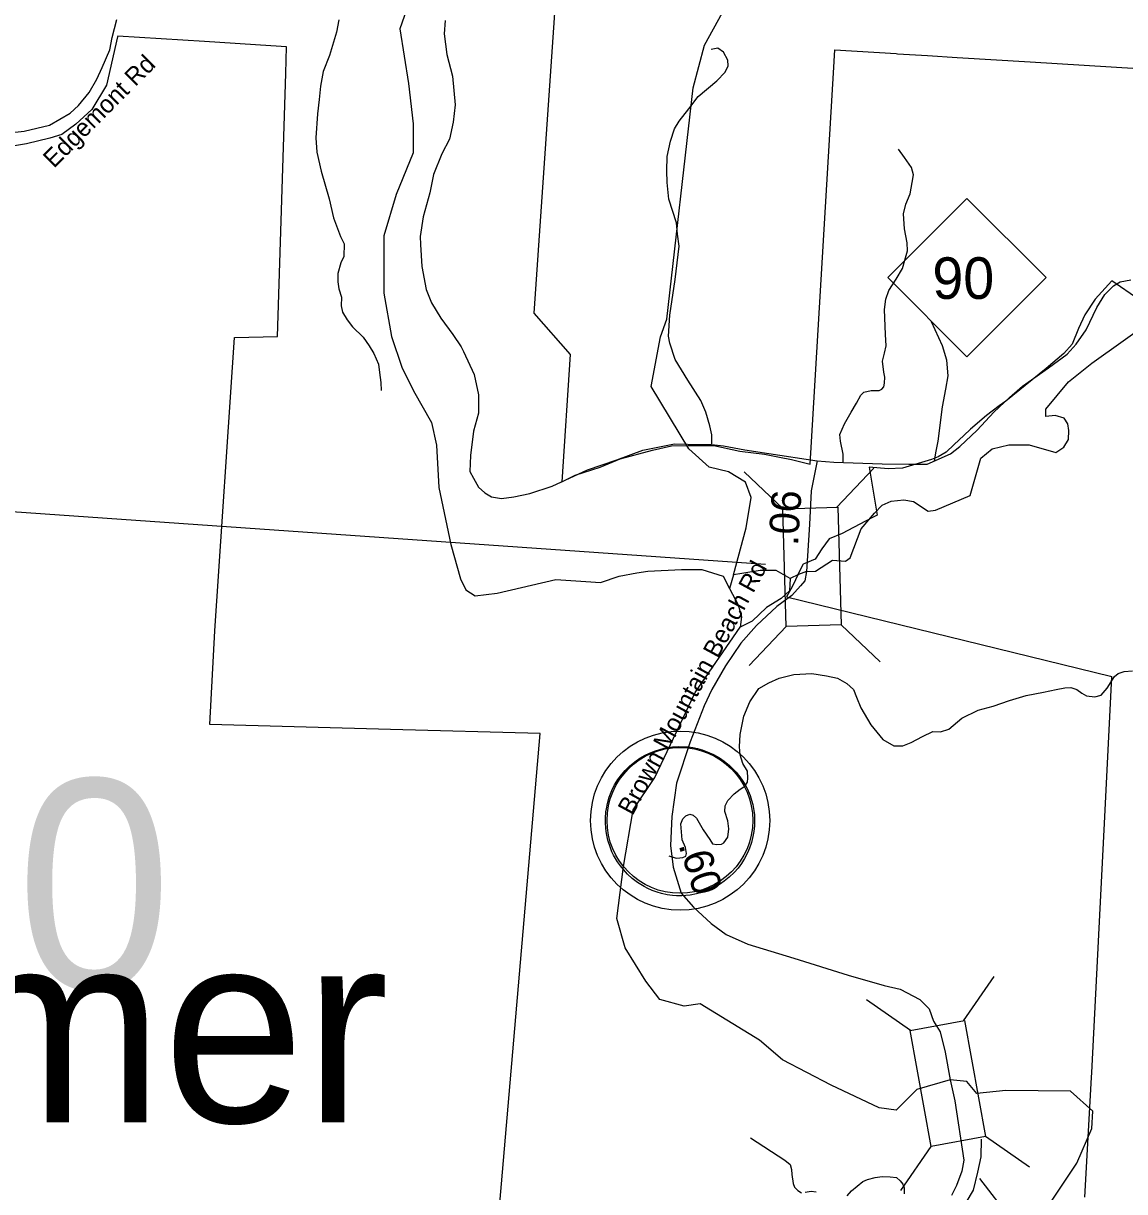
# Model space of a CAD drawing. Extents: x 1159738 to 1321356, y 736314 to 882035.
# Drawn here: x 1180449 to 1185086, y 823694 to 828611 of the extents above; entities that cross this region are included whole.
import ezdxf

# ---------------------------------------------------------------- set-up
doc = ezdxf.new("R2010")
doc.units = 0
for name, color, linetype in [('Exist Boundary Land Use Forest National US Forest Service', 7, 'Continuous'), ('Exist Civil Demographics Community CELL', 7, 'Continuous'), ('Exist Civil Demographics Community Label', 7, 'Continuous'), ('Exist Geographical Mountain Summit Elevation Number Label', 7, 'Continuous'), ('Exist Hydrographic Creek Single Shore', 7, 'Continuous'), ('Exist Road Non-System Type 51', 7, 'Continuous'), ('Exist Road Primary NC Label', 7, 'Continuous'), ('Exist Road Primary NC Shield CELL', 7, 'Continuous'), ('Exist Road Primary NC Shield Number Label', 7, 'Continuous'), ('Exist Road Primary NC Unpaved Attributed', 7, 'Continuous'), ('Exist Road Secondary Mileage Hundredths English Label', 7, 'Continuous'), ('Exist Road Secondary Structure Standard Bridge CELL', 7, 'Continuous'), ('Exist Road Secondary Structure Standard Bridge Number Label', 7, 'Continuous'), ('Exist Road Secondary Type 41 Attributed', 7, 'Continuous'), ('Exist Road Secondary Type 51 Label', 7, 'Continuous')]:
    doc.layers.add(name, color=color, linetype=linetype)

msp = doc.modelspace()

# ---------------------------------------------------------------- linework, layer by layer
at = {"layer": 'Exist Boundary Land Use Forest National US Forest Service'}
for points in [[(1182733.1, 829348.1), (1182598.4, 827391.9), (1182751.4, 827216.9), (1182716.4, 826681.9), (1182772.4, 826709.9), (1182877.4, 826742.9), (1182962.4, 826778.9), (1183097.4, 826814.9), (1183178.4, 826832.9), (1183248.3, 826834.9), (1183254, 826834.8), (1183356.4, 826833.9), (1183465.4, 826810.9), (1183569.3, 826797.9), (1183632.9, 826785.1), (1183683.3, 826774.9), (1183762.4, 826755.9), (1183859.6, 828403.4), (1183865.2, 828499.9), (1184123.6, 828483.9), (1184129.7, 828483.6), (1184255.3, 828475.7), (1184381, 828468), (1184688.9, 828448.9), (1185575.4, 828394)], [(1181077.2, 821985.4), (1181096, 822331.8), (1181167.4, 823654.7), (1182450.4, 823595.7), (1182625.4, 825621.8), (1181994.3, 825639.1), (1181234.4, 825659.8), (1181255.3, 826054.8), (1181338.3, 827288.9), (1181518.2, 827293.9), (1181553.8, 828399.8), (1181557.3, 828511.9), (1181490.6, 828516.2), (1181211.2, 828534.3), (1180846.2, 828557.9), (1180845.6, 828555), (1180799.3, 828350.9), (1180737.3, 828248.9), (1180670.2, 828186.9), (1180611.3, 828143.9), (1180560.2, 828127.9), (1180461.3, 828103.9), (1180360.3, 828086.9)], [(1185259.6, 827371), (1185032.4, 827526.9), (1184962.4, 827450.9), (1184918.4, 827383.9), (1184891.4, 827326.9), (1184865.4, 827260.9)], [(1184865.4, 827260.9), (1184830.4, 827221.9), (1184756.4, 827158), (1184586.4, 827020.9), (1184558.4, 827000.9), (1184504.4, 826960.9), (1184436.4, 826902.9), (1184408.6, 826876.6), (1184368.3, 826838.2), (1184334.4, 826805.9), (1184301.4, 826786.9), (1184273.4, 826775.9), (1184150.4, 826738.9), (1184090.4, 826736.9), (1184010.4, 826742.9), (1184044.3, 826541.9), (1184021, 826529.6), (1183994.4, 826515.6), (1183896.4, 826463.9), (1183841.3, 826441.9), (1183810.4, 826398.9), (1183783.4, 826355.9), (1183738.9, 826337.5), (1183732.4, 826334.9), (1183721.8, 826313.5), (1183688.4, 826245.9), (1183679.9, 826229.8), (1183662.3, 826196.9), (1185026.7, 825863), (1185031.4, 825861.9), (1185002.8, 825299.1), (1184946.4, 824195.8), (1184945.2, 824175.1), (1184917, 823671.3)]]:
    msp.add_lwpolyline(points, dxfattribs=at)
at = {"layer": 'Exist Civil Demographics Community CELL'}
msp.add_lwpolyline([(1182904, 825305.2), (1182908, 825327.5), (1182915.1, 825353.8), (1182926.8, 825382.6), (1182938.5, 825405.6), (1182951.8, 825428.5), (1182966.9, 825449), (1182982.7, 825466.5), (1183001.1, 825484.9), (1183023.2, 825503.3), (1183044.9, 825517.9), (1183064.4, 825529.3), (1183084.7, 825539.2), (1183106.5, 825548.3), (1183129, 825555.6), (1183146.4, 825560.2), (1183165.8, 825563.2), (1183182.3, 825566.1), (1183207.7, 825567.1), (1183225.5, 825566.7), (1183248.1, 825565.7), (1183267.7, 825562.7), (1183287.3, 825558.8), (1183307.4, 825553.1), (1183328, 825545.4), (1183354.6, 825533.7), (1183379.7, 825519.7), (1183399.9, 825505.5), (1183420.6, 825489.5), (1183433.9, 825477), (1183450.3, 825459.4), (1183465.8, 825440.6), (1183478.1, 825422.3), (1183490.6, 825402.2), (1183500.4, 825381.6), (1183508.6, 825361.5), (1183514.8, 825341.5), (1183520, 825323.1), (1183524.3, 825298.9), (1183526.8, 825280.1), (1183527.9, 825256.1), (1183527.2, 825233), (1183524.9, 825210.2), (1183521.1, 825188.3), (1183514.5, 825163.7), (1183507, 825140.3), (1183497.8, 825120.1), (1183485.2, 825096.1), (1183472.1, 825074.8), (1183458.3, 825056), (1183441.4, 825037), (1183420.2, 825017.2), (1183400.1, 825000.7), (1183380.1, 824986.9), (1183362.8, 824976.9), (1183335.6, 824963.9), (1183307, 824953.1), (1183283.2, 824947.2), (1183256.8, 824942), (1183239, 824940.1), (1183221.1, 824939.1), (1183198.7, 824939.1), (1183181.6, 824940.8), (1183159.1, 824943.7), (1183135.4, 824948.9), (1183117, 824954.1), (1183096.4, 824961.6), (1183078, 824969.6), (1183062.3, 824978.5), (1183035.1, 824994.8), (1183012.8, 825011.9), (1182993.2, 825029.9), (1182975.3, 825049.3), (1182962.6, 825065.2), (1182950.7, 825081.9), (1182934.3, 825110.2), (1182927.4, 825124.4), (1182920.5, 825140.5), (1182910.2, 825173.3), (1182904, 825201.5), (1182901.3, 825222.1), (1182900, 825247.4), (1182899.8, 825266.2), (1182901.9, 825292)], close=True, dxfattribs=at)
for centre, radius in [((1183214.5, 825255.5), 377.3), ((1183213.4, 825256.6), 306.8)]:
    msp.add_circle(centre, radius, dxfattribs=at)
at = {"layer": 'Exist Hydrographic Creek Single Shore'}
for points in [[(1183438.9, 826290.1), (1183492.7, 826487.5), (1183513.2, 826615.7), (1183490.1, 826679.8), (1183418.4, 826723.3), (1183336.4, 826743.8), (1183251.3, 826819.8), (1183092.3, 827082.3), (1183131.3, 827291.7), (1183158.3, 827366.6), (1183269.3, 828339.3), (1183316.3, 828518.9), (1183430.3, 828726.7), (1183749.3, 829091.2), (1184045.3, 829551.4), (1184334, 830291.9)], [(1182080, 828722), (1182033.9, 828588.7), (1182069.8, 828358), (1182090.3, 828188.8), (1182090.3, 828065.7), (1182018.6, 827891.4), (1181967.3, 827717.1), (1181967.3, 827476.1), (1181999.2, 827293.2), (1182041.8, 827164.3), (1182091.8, 827065.2), (1182167.2, 826931.2), (1182188.8, 826836.4), (1182197.6, 826658.4), (1182248.9, 826417.4), (1182289.9, 826273.8), (1182312.5, 826227.5), (1182351.3, 826202.1), (1182443.6, 826212.3), (1182690.4, 826271), (1182817.9, 826262.4), (1182879.1, 826257.2), (1182957.1, 826284.3), (1183031.3, 826299), (1183077.8, 826305.9), (1183220, 826311.9), (1183305.3, 826311.9), (1183395.8, 826284.3), (1183422.2, 826232.8)], [(1183746.8, 826303.7), (1183784.5, 826305.9), (1183856.1, 826351.6), (1183910.4, 826347.3), (1183930.6, 826362.1), (1183976.7, 826484.3), (1184033.1, 826549.3), (1184064.6, 826583.4), (1184102.6, 826599.8), (1184156, 826605.7), (1184197.4, 826598.1), (1184258.6, 826557.6), (1184289.6, 826561.9), (1184435.3, 826623.6), (1184480.9, 826780.8), (1184528.3, 826820.4), (1184599, 826837.7), (1184684.3, 826837.7), (1184796.8, 826805.3), (1184830.4, 826826.9), (1184849.4, 826859.6), (1184851.1, 826897.6), (1184846.8, 826926), (1184832.1, 826949.3), (1184793.7, 826961.2), (1184754.6, 826957), (1184754.6, 826988.1), (1184850.1, 827102.2), (1184947.4, 827181.7), (1185465.4, 827550.3)], [(1183677.1, 826274.7), (1183618.2, 826308), (1183551.6, 826308), (1183474.7, 826295.2), (1183438.9, 826290.1)], [(1183746.8, 826303.7), (1183712.1, 826292.1), (1183677.1, 826274.7), (1183674.6, 826223.4), (1183639.6, 826191), (1183578, 826152.6), (1183518.3, 826095.2), (1183467, 826069.6)], [(1183438.9, 826290.1), (1183422.2, 826232.8)], [(1183422.2, 826232.8), (1183459.4, 826164.5), (1183472.2, 826113.2), (1183467, 826069.6)], [(1184351.6, 824164.1), (1184211.7, 824124.2), (1184124.4, 824036.9), (1184053, 824046.8), (1183850.5, 824142.4), (1183645.4, 824248.2), (1183548.7, 824332.2), (1183298.2, 824484.8), (1183231.6, 824474.6), (1183129.1, 824502.8), (1183070.2, 824579.7), (1182983.1, 824720.7), (1182947.2, 824843.7), (1182975.3, 825063.2), (1183016.3, 825301.6), (1183108.5, 825437.5), (1183277.5, 825795.3), (1183467, 826069.6)], [(1184640.4, 823447.1), (1184884.4, 823813.2), (1184947.5, 823960.4), (1184952.6, 824032.2), (1184857.8, 824116.8), (1184586.3, 824119.4), (1184463.3, 824106.6), (1184422.3, 824157.8), (1184351.6, 824164.1)]]:
    msp.add_lwpolyline(points, dxfattribs=at)
at = {"layer": 'Exist Road Non-System Type 51'}
for points in [[(1181776.6, 828625.5), (1181767, 828574), (1181738.1, 828475.5), (1181711.3, 828409.1), (1181699.6, 828347), (1181694.2, 828290.2), (1181687.8, 828230.3), (1181680.4, 828129.3), (1181684.6, 828069.3), (1181702.8, 827989), (1181736, 827873.3), (1181754.2, 827793), (1181784, 827714.6), (1181800.1, 827683.5), (1181798, 827630), (1181786.2, 827603.2), (1181773.3, 827558.2), (1181772.3, 827522.9), (1181776.6, 827494), (1181788.3, 827458.6), (1181787.3, 827422.2), (1181792.6, 827395.4), (1181811.8, 827363.8), (1181834.2, 827333.8), (1181880.2, 827289.9), (1181904.9, 827254.6), (1181925.2, 827221.4), (1181944.5, 827176.4), (1181948.7, 827142.1), (1181954.1, 827100.3), (1181955.2, 827066.1)], [(1183348.4, 826841.3), (1183348.4, 826879.8), (1183339.8, 826917.3), (1183322.7, 826975.1), (1183301.3, 827024.4), (1183246.7, 827109), (1183193.2, 827196.8), (1183171, 827264.8), (1183165.7, 827294.8), (1183171, 827382.6), (1183193.5, 827533.6), (1183210.6, 827672.8), (1183203.1, 827724.2), (1183198.8, 827771.3), (1183166.8, 827871.2), (1183159.3, 827940.8), (1183158.2, 827991.1), (1183159.3, 828051.1), (1183174.3, 828115.3), (1183190.3, 828166.7), (1183210.7, 828199.9), (1183251.3, 828251.3), (1183289.7, 828304.1), (1183368.9, 828369.4), (1183404.2, 828405.8), (1183416, 828432.6), (1183414.9, 828456.1), (1183396.7, 828490.4), (1183373.2, 828506.5), (1183345.3, 828501.1)], [(1183901, 826762.3), (1183901, 826798.7), (1183889.2, 826853.4), (1183887, 826881.2), (1183906.3, 826926.2), (1183934.1, 826975.4), (1183956.6, 827012.9), (1183975.9, 827046.1), (1183987.6, 827059), (1184018.7, 827065.4), (1184052.9, 827065.4), (1184063.6, 827071.8), (1184072.2, 827081.5), (1184075.4, 827097.5), (1184076.5, 827122.2), (1184072.2, 827142.5), (1184066.8, 827189.6), (1184075.4, 827222.8), (1184081.8, 827253.9), (1184078.6, 827301), (1184074.3, 827407.4), (1184080.7, 827450.2), (1184093.6, 827486.6), (1184124.6, 827534.8), (1184150.3, 827579.8), (1184161, 827615.1), (1184171.7, 827653.7), (1184170.6, 827686.9), (1184158.9, 827746.9), (1184154.6, 827809.1), (1184165.3, 827850.9), (1184183.5, 827893.7), (1184192, 827941.9), (1184197.4, 827974), (1184188.8, 828004), (1184158.8, 828046.9), (1184133.2, 828081.1)], [(1184286, 826766.7), (1184291.4, 826803.1), (1184301, 826852.4), (1184319.2, 826996.7), (1184333.1, 827071.7), (1184342.8, 827128.4), (1184337.4, 827193.8), (1184319.2, 827253.7), (1184273.2, 827355.5)], [(1183167.1, 825108), (1183197.8, 825098.1), (1183212.5, 825099.4), (1183226, 825100.6), (1183238.3, 825105.5), (1183240.8, 825116.6), (1183237.1, 825142.4), (1183223.6, 825174.3), (1183217.4, 825241.9), (1183226, 825262.8), (1183238.3, 825276.3), (1183255.5, 825282.5), (1183269, 825278.8), (1183283.7, 825266.5), (1183310.8, 825217.3), (1183339, 825175.6), (1183351.3, 825158.4), (1183368.5, 825154.7), (1183388.1, 825155.9), (1183398, 825162), (1183415.1, 825185.4), (1183418.8, 825221), (1183415.1, 825254.2), (1183402.9, 825293.5), (1183404.1, 825318.1), (1183415.1, 825340.2), (1183442.2, 825368.5), (1183466.7, 825388.2), (1183486.4, 825400.4), (1183497.4, 825417.7), (1183499.9, 825434.9), (1183498.7, 825464.3), (1183477.8, 825496.3), (1183466.7, 825533.2), (1183464.3, 825566.3), (1183467.7, 825618.6), (1183482.5, 825694.8), (1183508.3, 825755.1), (1183546.3, 825811.6), (1183588.1, 825834.9), (1183631.1, 825855.8), (1183693.7, 825870.6), (1183768.6, 825874.3), (1183831.2, 825865.7), (1183876.7, 825854.6), (1183916, 825832.5), (1183944.2, 825807.9), (1183956.5, 825775.9), (1183974.9, 825730.5), (1184016.7, 825659.2), (1184068.3, 825596.5), (1184114.9, 825570.7), (1184151.8, 825570.7), (1184187.4, 825584.2), (1184235.3, 825610), (1184278.3, 825630.9), (1184311.4, 825629.7), (1184345.8, 825640.8), (1184400.3, 825687.1), (1184469.1, 825720.3), (1184532.9, 825737.5), (1184601.7, 825760.8), (1184671.7, 825781.7), (1184744.1, 825796.4), (1184798.2, 825807.5), (1184835, 825814.9), (1184859.6, 825816.1), (1184885.4, 825807.5), (1184906.2, 825791.5), (1184925.9, 825780.5), (1184960.3, 825776.8), (1184987.3, 825784.2), (1185013.1, 825813.6), (1185043.8, 825861.6), (1185058.5, 825875.1), (1185084.3, 825883.7), (1185119.9, 825886.2)], [(1183510.4, 823920.4), (1183655.6, 823826.9), (1183677, 823807.8), (1183683.6, 823787.6), (1183684.8, 823766.1), (1183690.1, 823728.6), (1183696.1, 823713.1), (1183710.4, 823698.2), (1183725.8, 823688.7)], [(1184419, 823648.5), (1184449.5, 823700), (1184468.1, 823775.5), (1184481.5, 823840.3), (1184483.4, 823914.8)], [(1183917.7, 823676.2), (1183936.2, 823697.6), (1183983.8, 823736.4), (1184004, 823745.3), (1184036.2, 823754.2), (1184065.3, 823757.2), (1184098.6, 823756.6), (1184124.8, 823754.2), (1184140.8, 823739.5), (1184152.1, 823725.3), (1184158, 823709.8), (1184157.4, 823685.4)], [(1183740.7, 823691.1), (1183766.3, 823695.9), (1183787.1, 823693.5)]]:
    msp.add_lwpolyline(points, dxfattribs=at)
at = {"layer": 'Exist Road Primary NC Shield CELL'}
msp.add_lwpolyline([(1184089.3, 827541.3), (1184422.3, 827874.3), (1184755.3, 827541.3), (1184422.3, 827208.3)], close=True, dxfattribs=at)
at = {"layer": 'Exist Road Primary NC Unpaved Attributed'}
for points in [[(1180375, 828148.6), (1180452.5, 828158), (1180559, 828182.6), (1180645.2, 828232.6), (1180680.5, 828266.2), (1180725.3, 828320.5), (1180758.1, 828375.7), (1180780, 828426.1), (1180812.8, 828499.3), (1180822.9, 828551.2), (1180841.7, 828628.2)], [(1182225, 828623), (1182220.7, 828567.9), (1182231.9, 828480.8), (1182255.3, 828389.7), (1182266.7, 828268.9), (1182258.2, 828195.1), (1182243.5, 828123.6), (1182211.2, 828061.9), (1182175.8, 827975.8), (1182159.7, 827898), (1182132.5, 827796.5), (1182119.4, 827714.2), (1182120.7, 827680.1), (1182126.3, 827587.5), (1182145.3, 827491.8), (1182166.8, 827434.9), (1182206.9, 827369.9), (1182256.9, 827301.8), (1182292.2, 827250.1), (1182301.7, 827230.2), (1182346.8, 827133.8), (1182365.1, 827047.7), (1182365.1, 826970.5), (1182343.7, 826894.8), (1182331.4, 826792), (1182328.8, 826725.6), (1182343.5, 826697.2), (1182365, 826659.3), (1182391.3, 826635.5), (1182419.8, 826618.3), (1182462, 826611.4), (1182514.6, 826618.3), (1182581.4, 826632.2), (1182675.7, 826663.7), (1182823.7, 826731.8), (1182947.3, 826774.6), (1183057.5, 826814.8), (1183190.3, 826841.5), (1183301.9, 826839.4), (1183346.7, 826839.4), (1183396.7, 826832.5), (1183486.3, 826816.1), (1183588, 826801.5), (1183791, 826770.4)], [(1183791, 826770.4), (1183861.7, 826764.8), (1184065.5, 826757.5), (1184176.7, 826756.6), (1184254.3, 826756.6), (1184352.5, 826798.9), (1184392.2, 826830.8), (1184464.5, 826899.7), (1184534.8, 826974.3), (1184602, 827036.3), (1184656.3, 827083.7), (1184764.9, 827161.3), (1184843.8, 827218.6), (1184882.6, 827261.7), (1184924.8, 827321.2), (1184969.6, 827416), (1185002.8, 827470.7), (1185039, 827506.9), (1185067.4, 827523.3), (1185112.2, 827531.9)]]:
    msp.add_lwpolyline(points, dxfattribs=at)
at = {"layer": 'Exist Road Secondary Structure Standard Bridge CELL'}
for p, q in [((1183874.6, 826574.5), (1184030.2, 826738.9)), ((1183648.3, 826568.3), (1183483.9, 826724)), ((1183505.1, 825908.4), (1183660.7, 826072.7)), ((1184056.6, 825923.4), (1183892.2, 826079)), ((1184407.3, 824413), (1184536.1, 824599.1)), ((1184184.5, 824372.5), (1183998.5, 824501.4)), ((1184143.2, 823698.5), (1184272.1, 823884.6)), ((1184686, 823797.1), (1184500, 823925.9))]:
    msp.add_line(p, q, dxfattribs=at)
for points in [[(1183660.7, 826072.7), (1183647.2, 826568.3), (1183878.7, 826574.6), (1183892.2, 826079)], [(1184272.1, 823884.6), (1184183.5, 824372.3), (1184411.3, 824413.7), (1184500, 823925.9)]]:
    msp.add_lwpolyline(points, close=True, dxfattribs=at)
at = {"layer": 'Exist Road Secondary Structure Standard Bridge Number Label'}
msp.add_line((1184475.5, 823749), (1186641.8, 820957.8), dxfattribs=at)
msp.add_lwpolyline([(1183574.4, 826333.4), (1180077.9, 826577.3), (1172027.9, 828935.5)], dxfattribs=at)
at = {"layer": 'Exist Road Secondary Type 41 Attributed'}
for points in [[(1183791, 826770.4), (1183766.5, 826643.4), (1183759.4, 826501.5), (1183746.8, 826303.7)], [(1183746.8, 826303.7), (1183739.7, 826264.3), (1183720.9, 826243.8), (1183685.2, 826202.6), (1183621.9, 826156.5), (1183536.2, 826076.5), (1183470.5, 826002.1), (1183404.8, 825907.8), (1183347.6, 825807.7), (1183316.2, 825739.1), (1183256.2, 825587.5), (1183199, 825413.1), (1183179, 825273), (1183173.3, 825150.9), (1183184.8, 825059.4), (1183219.1, 824950.8), (1183270.5, 824890.7), (1183344.8, 824822.1), (1183407.6, 824776.3), (1183499.1, 824736.3), (1183693.4, 824676.3), (1183921.9, 824604.8), (1184073.4, 824561.9), (1184140.7, 824546), (1184223.6, 824503.1), (1184263.6, 824463.1), (1184280.7, 824411.6), (1184309, 824366.5), (1184330.8, 824281.1), (1184351.6, 824164.1)], [(1184351.6, 824164.1), (1184370.5, 824076.6), (1184409.2, 823826), (1184400.6, 823780.3), (1184377.7, 823720.2), (1184357.7, 823677.4)]]:
    msp.add_lwpolyline(points, dxfattribs=at)

# ---------------------------------------------------------------- texts
at = {"layer": 'Exist Civil Demographics Community Label'}
msp.add_text('Mortimer', height=800, dxfattribs=at).set_placement((1177768.8, 823985.4))
at = {"layer": 'Exist Geographical Mountain Summit Elevation Number Label'}
msp.add_text('Elev. 2470', height=880, dxfattribs=at).set_placement((1175513.1, 824549.1))
at = {"layer": 'Exist Road Primary NC Label'}
msp.add_text('Edgemont Rd', height=75, rotation=45.0327, dxfattribs=at).set_placement((1180577.2, 827998.8))
at = {"layer": 'Exist Road Primary NC Shield Number Label'}
msp.add_text('90', height=175, dxfattribs=at).set_placement((1184276.5, 827451.6))
at = {"layer": 'Exist Road Secondary Mileage Hundredths English Label'}
for s, rotation, p in [('.06', 86.1026, (1183710.3, 826410.5)), ('.60', 287.5134, (1183206.5, 825153.9))]:
    msp.add_text(s, height=125, rotation=rotation, dxfattribs=at).set_placement(p)
at = {"layer": 'Exist Road Secondary Type 51 Label'}
msp.add_text('Brown Mountain Beach Rd', height=75, rotation=61.5068, dxfattribs=at).set_placement((1183013.8, 825273.7))

doc.saveas('drawing.dxf')
